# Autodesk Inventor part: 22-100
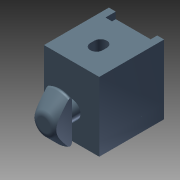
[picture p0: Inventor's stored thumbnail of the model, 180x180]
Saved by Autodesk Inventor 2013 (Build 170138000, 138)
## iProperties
Created: 2004-11
Part Number: 22-100
Document SubType Name: Modeling
Designer: Autodesk, Inc.
Manufacturer: Standard
Standards Organization: Custom
Description: MULTIBLOCK PA 40, M6
Catalog Web Link: http://www.parker.com/ead/cm1.asp?cmid=809
Vendor: PARKER IPS
Mass: 11.6679 g
Surface Area: 40.4077 cm^2
Volume: 11.6679 cm^3
Density: 1 g/cm^3
Material: Allgemein
CAGE: 1LJX3
Dept. ID: Product Design
Description #2: ---
Finish #1: ---
Finish #2: ---
Material ID: ---
Project Number: ---
Description: Multiblock PA 40
Order Number: 22-100
Selection: Multiblock PA 40, M6
Supplier: Parker Hannifin Corp., Industrial Profile Systems Div.
Author: Autodesk, Inc.
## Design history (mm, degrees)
feature "Base1"
body "Solid1"
